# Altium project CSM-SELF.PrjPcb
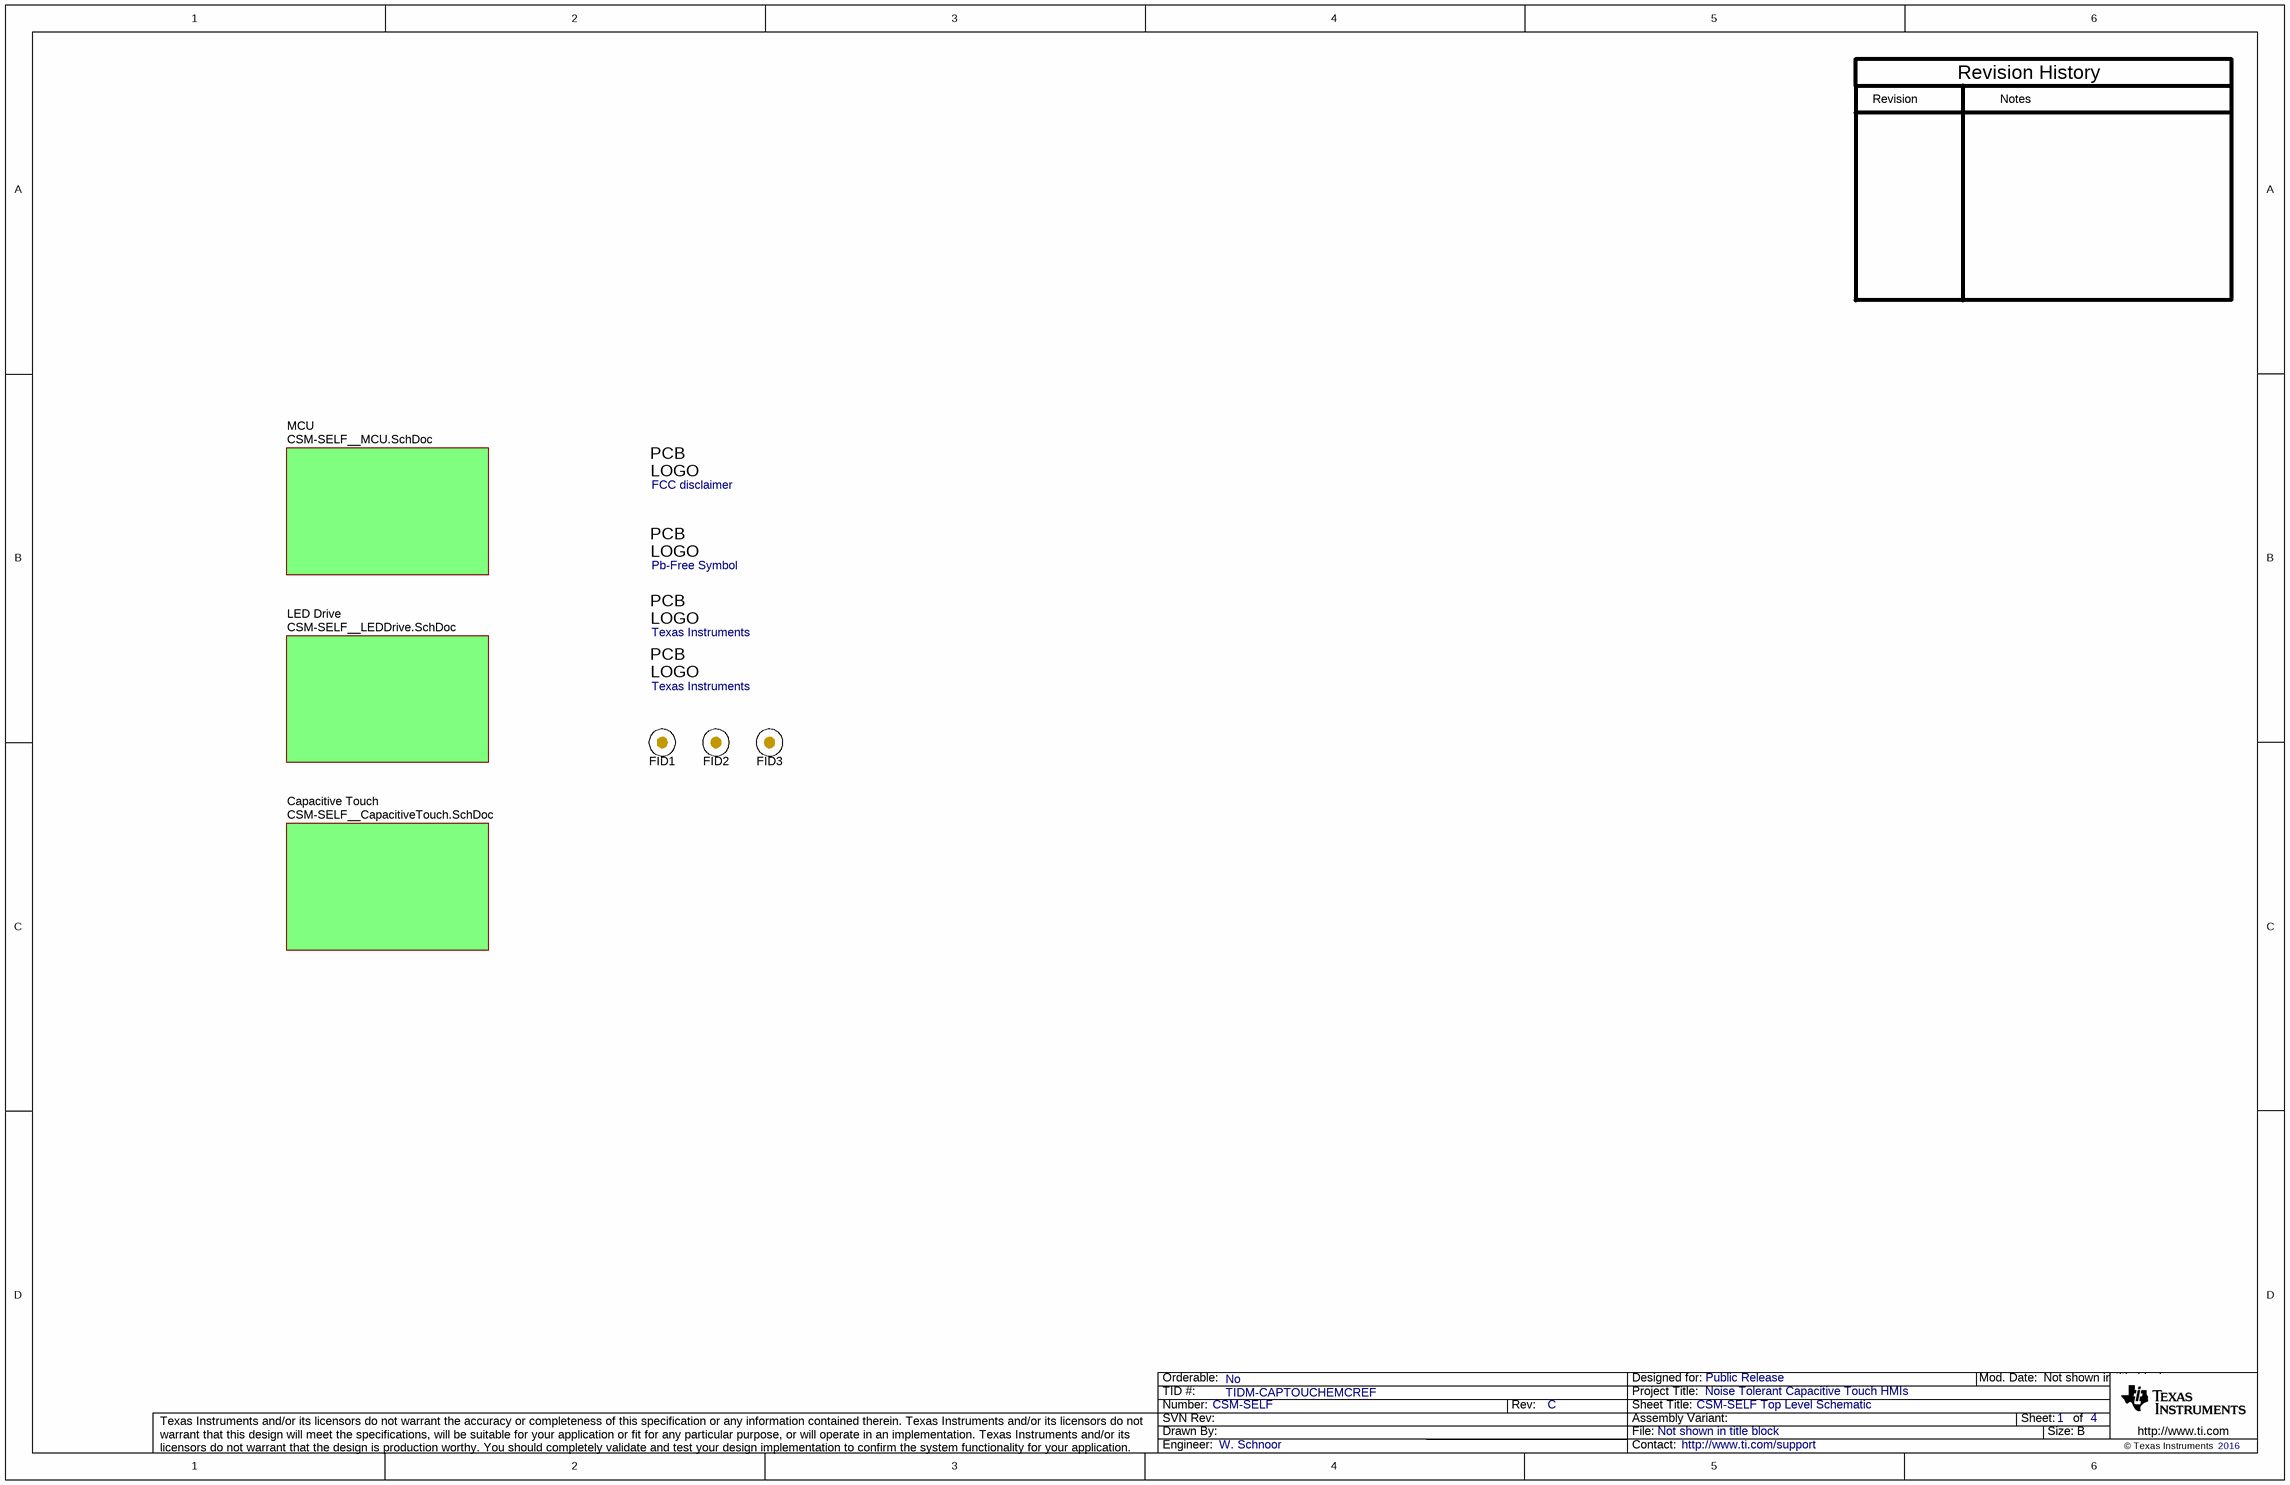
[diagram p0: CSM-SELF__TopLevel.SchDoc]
TID: TIDM-CAPTOUCHEMCREF; TechSupport: http://www.ti.com/support; SCH_Rev: C; PRJ_Title: Noise Tolerant Capacitive Touch HMIs; PRJ_Number: CSM-SELF; PRJ_Engineer: W. Schnoor; PRJ_Customer: Public Release; PCB_Rev: C; PCB_Layout: W. Schnoor; EVM_Orderable: No; CopyrightYear: 2016
4 sheets, 115 parts. Net scope: global (net labels, ports and power ports of the same name join across sheets).
Board file: CSM-SELF.PcbDoc
Sheets:
  CSM-SELF__TopLevel.SchDoc
    Capacitive Touch = CSM-SELF__CapacitiveTouch.SchDoc
    LED Drive = CSM-SELF__LEDDrive.SchDoc
    MCU = CSM-SELF__MCU.SchDoc

## Sheet CSM-SELF__TopLevel.SchDoc: CSM-SELF Top Level Schematic
size 431 x 279 mm; Date: Not shown in title block; ApprovedBy: Not shown in title block; CheckedBy: Not shown in title block; Author: Not shown in title block; CompanyName: Not shown in title block; Engineer: Not shown in title block; Organization: Not shown in title block; Address1: Not shown in title block; Address2: Not shown in title block; Address3: Not shown in title block; Address4: Not shown in title block; DocumentNumber: 1; Revision: Use project parameter SCH_Rev; SheetNumber: 1; SheetTotal: 4; PageSetup: Record=PageOptions¦CenterHorizontal=True¦CenterVertical=True¦PrintScale=1.00¦XCorrection=1.00¦YCorrection=1.00¦PrintKind=0¦BorderSize=5000000¦LeftOffset=0¦BottomOffset=0¦Orientation=2¦PaperLength=1000¦PaperWidth=1000¦Scale=100¦PaperSource=15¦PrintQuality=600¦MediaType=1¦DitherType=10¦PaperKind=Letter¦PrintScaleMode=1

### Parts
FCCLogo  FCC disclaimer  [FCC_disclaimer]  (no BOM)
FID1  Fiducial  [Fiducial10-30]  (value not drawn)
FID2  Fiducial  [Fiducial10-30]  (value not drawn)
FID3  Fiducial  [Fiducial10-30]  (value not drawn)
PbFreeLogo  Pb-Free Symbol  [Pb-Free_Overlay_Medium]  (no BOM)
TILogo  Texas Instruments  [TI_Stacked_Overlay_Medium]  (no BOM)
TILogoBack  Texas Instruments  [TI_Stacked_Overlay_Medium]  (no BOM)

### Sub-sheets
Capacitive Touch = CSM-SELF__CapacitiveTouch.SchDoc: no entries
LED Drive = CSM-SELF__LEDDrive.SchDoc: no entries
MCU = CSM-SELF__MCU.SchDoc: no entries

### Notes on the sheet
- Revision
- Notes
- Revision History

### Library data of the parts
FCCLogo = FCC_disclaimer: SymbolCreator: codlsc
FID1-FID3 = Fiducial: Fiducial mark.  There is nothing to buy or mount.; SymbolCreator: codlsc
PbFreeLogo = Pb-Free: SymbolCreator: a0412235
TILogo TILogoBack = TI_Logo: Texas Instrument Corporate Signature; SymbolCreator: a0412235

## Sheet CSM-SELF__CapacitiveTouch.SchDoc: CSM-SELF Capacitive Touch Schematic
size 431 x 279 mm; Date: Not shown in title block; ApprovedBy: Not shown in title block; CheckedBy: Not shown in title block; Author: Not shown in title block; CompanyName: Not shown in title block; DrawnBy: W. Schnoor; Engineer: Not shown in title block; Organization: Not shown in title block; Address1: Not shown in title block; Address2: Not shown in title block; Address3: Not shown in title block; Address4: Not shown in title block; DocumentNumber: 1; Revision: Use project parameter SCH_Rev; SheetNumber: 2; SheetTotal: 4; PageSetup: Record=PageOptions¦CenterHorizontal=True¦CenterVertical=True¦PrintScale=1.00¦XCorrection=1.00¦YCorrection=1.00¦PrintKind=0¦BorderSize=5000000¦LeftOffset=0¦BottomOffset=0¦Orientation=2¦PaperLength=1000¦PaperWidth=1000¦Scale=100¦PaperSource=15¦PrintQuality=600¦MediaType=1¦DitherType=10¦PaperKind=Letter¦PrintScaleMode=1
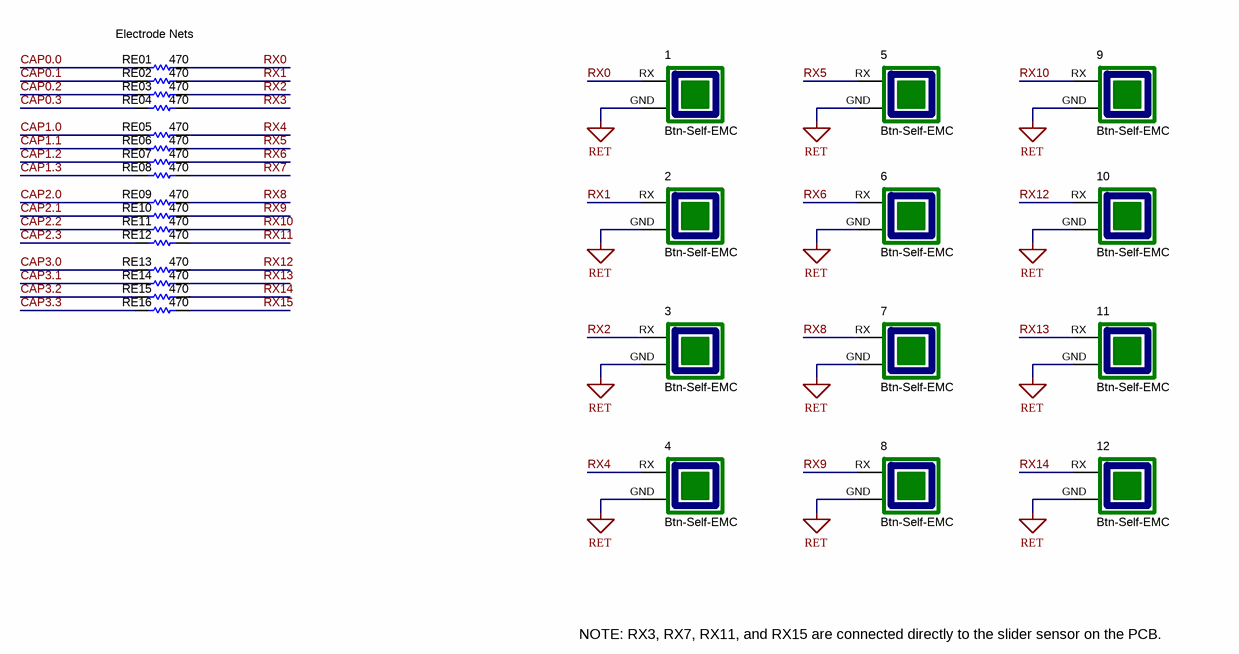
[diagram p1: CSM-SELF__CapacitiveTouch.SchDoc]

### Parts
1  Btn-Self-EMC  [btn-self-emc]
2  Btn-Self-EMC  [btn-self-emc]
3  Btn-Self-EMC  [btn-self-emc]
4  Btn-Self-EMC  [btn-self-emc]
5  Btn-Self-EMC  [btn-self-emc]
6  Btn-Self-EMC  [btn-self-emc]
7  Btn-Self-EMC  [btn-self-emc]
8  Btn-Self-EMC  [btn-self-emc]
9  Btn-Self-EMC  [btn-self-emc]
10  Btn-Self-EMC  [btn-self-emc]
11  Btn-Self-EMC  [btn-self-emc]
12  Btn-Self-EMC  [btn-self-emc]
RE01  ValueDisplayed: 470  [0402]  (hidden comment: CRCW0402470RJNED)
RE02  ValueDisplayed: 470  [0402]  (hidden comment: CRCW0402470RJNED)
RE03  ValueDisplayed: 470  [0402]  (hidden comment: CRCW0402470RJNED)
RE04  ValueDisplayed: 470  [0402]  (hidden comment: CRCW0402470RJNED)
RE05  ValueDisplayed: 470  [0402]  (hidden comment: CRCW0402470RJNED)
RE06  ValueDisplayed: 470  [0402]  (hidden comment: CRCW0402470RJNED)
RE07  ValueDisplayed: 470  [0402]  (hidden comment: CRCW0402470RJNED)
RE08  ValueDisplayed: 470  [0402]  (hidden comment: CRCW0402470RJNED)
RE09  ValueDisplayed: 470  [0402]  (hidden comment: CRCW0402470RJNED)
RE10  ValueDisplayed: 470  [0402]  (hidden comment: CRCW0402470RJNED)
RE11  ValueDisplayed: 470  [0402]  (hidden comment: CRCW0402470RJNED)
RE12  ValueDisplayed: 470  [0402]  (hidden comment: CRCW0402470RJNED)
RE13  ValueDisplayed: 470  [0402]  (hidden comment: CRCW0402470RJNED)
RE14  ValueDisplayed: 470  [0402]  (hidden comment: CRCW0402470RJNED)
RE15  ValueDisplayed: 470  [0402]  (hidden comment: CRCW0402470RJNED)
RE16  ValueDisplayed: 470  [0402]  (hidden comment: CRCW0402470RJNED)

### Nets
RET: 1.GND 2.GND 3.GND 4.GND 5.GND 6.GND 7.GND 8.GND 9.GND 10.GND 11.GND 12.GND
CAP0.0: RE01.1
CAP0.1: RE02.1
CAP0.2: RE03.1
CAP0.3: RE04.1
CAP1.0: RE05.1
CAP1.1: RE06.1
CAP1.2: RE07.1
CAP1.3: RE08.1
CAP2.0: RE09.1
CAP2.1: RE10.1
CAP2.2: RE11.1
CAP2.3: RE12.1
CAP3.0: RE13.1
CAP3.1: RE14.1
CAP3.2: RE15.1
CAP3.3: RE16.1
RX0: 1.RX RE01.2
RX1: 2.RX RE02.2
RX2: 3.RX RE03.2
RX3: RE04.2
RX4: 4.RX RE05.2
RX5: 5.RX RE06.2
RX6: 6.RX RE07.2
RX7: RE08.2
RX8: 7.RX RE09.2
RX9: 8.RX RE10.2
RX10: 9.RX RE11.2
RX11: RE12.2
RX12: 10.RX RE13.2
RX13: 11.RX RE14.2
RX14: 12.RX RE15.2
RX15: RE16.2

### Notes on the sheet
- Electrode Nets
- NOTE: RX3, RX7, RX11, and RX15 are connected directly to the slider sensor on the PCB.

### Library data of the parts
1-12 = btn-self-emc: Capacitive Button, Self Capacitance, 2-Layer, High EMC; Manufacturer: Used in BOM report; SymbolCreator: Use a-id; CompType: Used in some BOM reports.  Useful for finding later.; U/M: EA, IN, or GM
RE01 RE02 RE03 RE04 RE05 RE06 RE07 RE08 RE09-RE16 = CRCW0402470RJNED: RES, 470, 5%, 0.063 W, 0402; Manufacturer: Vishay-Dale; CompType: Resistor; Value: 470; Value_Code: 470R; Tolerance_%: 5; Power_W: 0.063; Value2: 0.063W; VDC_V: 50; TempCo: 200 ppm/C; EIA_Code: E24; U/M: EA; AEC Category: Q200

## Sheet CSM-SELF__LEDDrive.SchDoc
size 431 x 279 mm; Date: Not shown in title block; ApprovedBy: Not shown in title block; CheckedBy: Not shown in title block; Author: Not shown in title block; CompanyName: Not shown in title block; DrawnBy: W. Schnoor; Engineer: Not shown in title block; Organization: Not shown in title block; Address1: Not shown in title block; Address2: Not shown in title block; Address3: Not shown in title block; Address4: Not shown in title block; DocumentNumber: 1; Revision: Use project parameter SCH_Rev; SheetNumber: 3; SheetTotal: 4; PageSetup: Record=PageOptions¦CenterHorizontal=True¦CenterVertical=True¦PrintScale=1.00¦XCorrection=1.00¦YCorrection=1.00¦PrintKind=0¦BorderSize=5000000¦LeftOffset=0¦BottomOffset=0¦Orientation=2¦PaperLength=1000¦PaperWidth=1000¦Scale=100¦PaperSource=15¦PrintQuality=600¦MediaType=1¦DitherType=10¦PaperKind=Letter¦PrintScaleMode=1
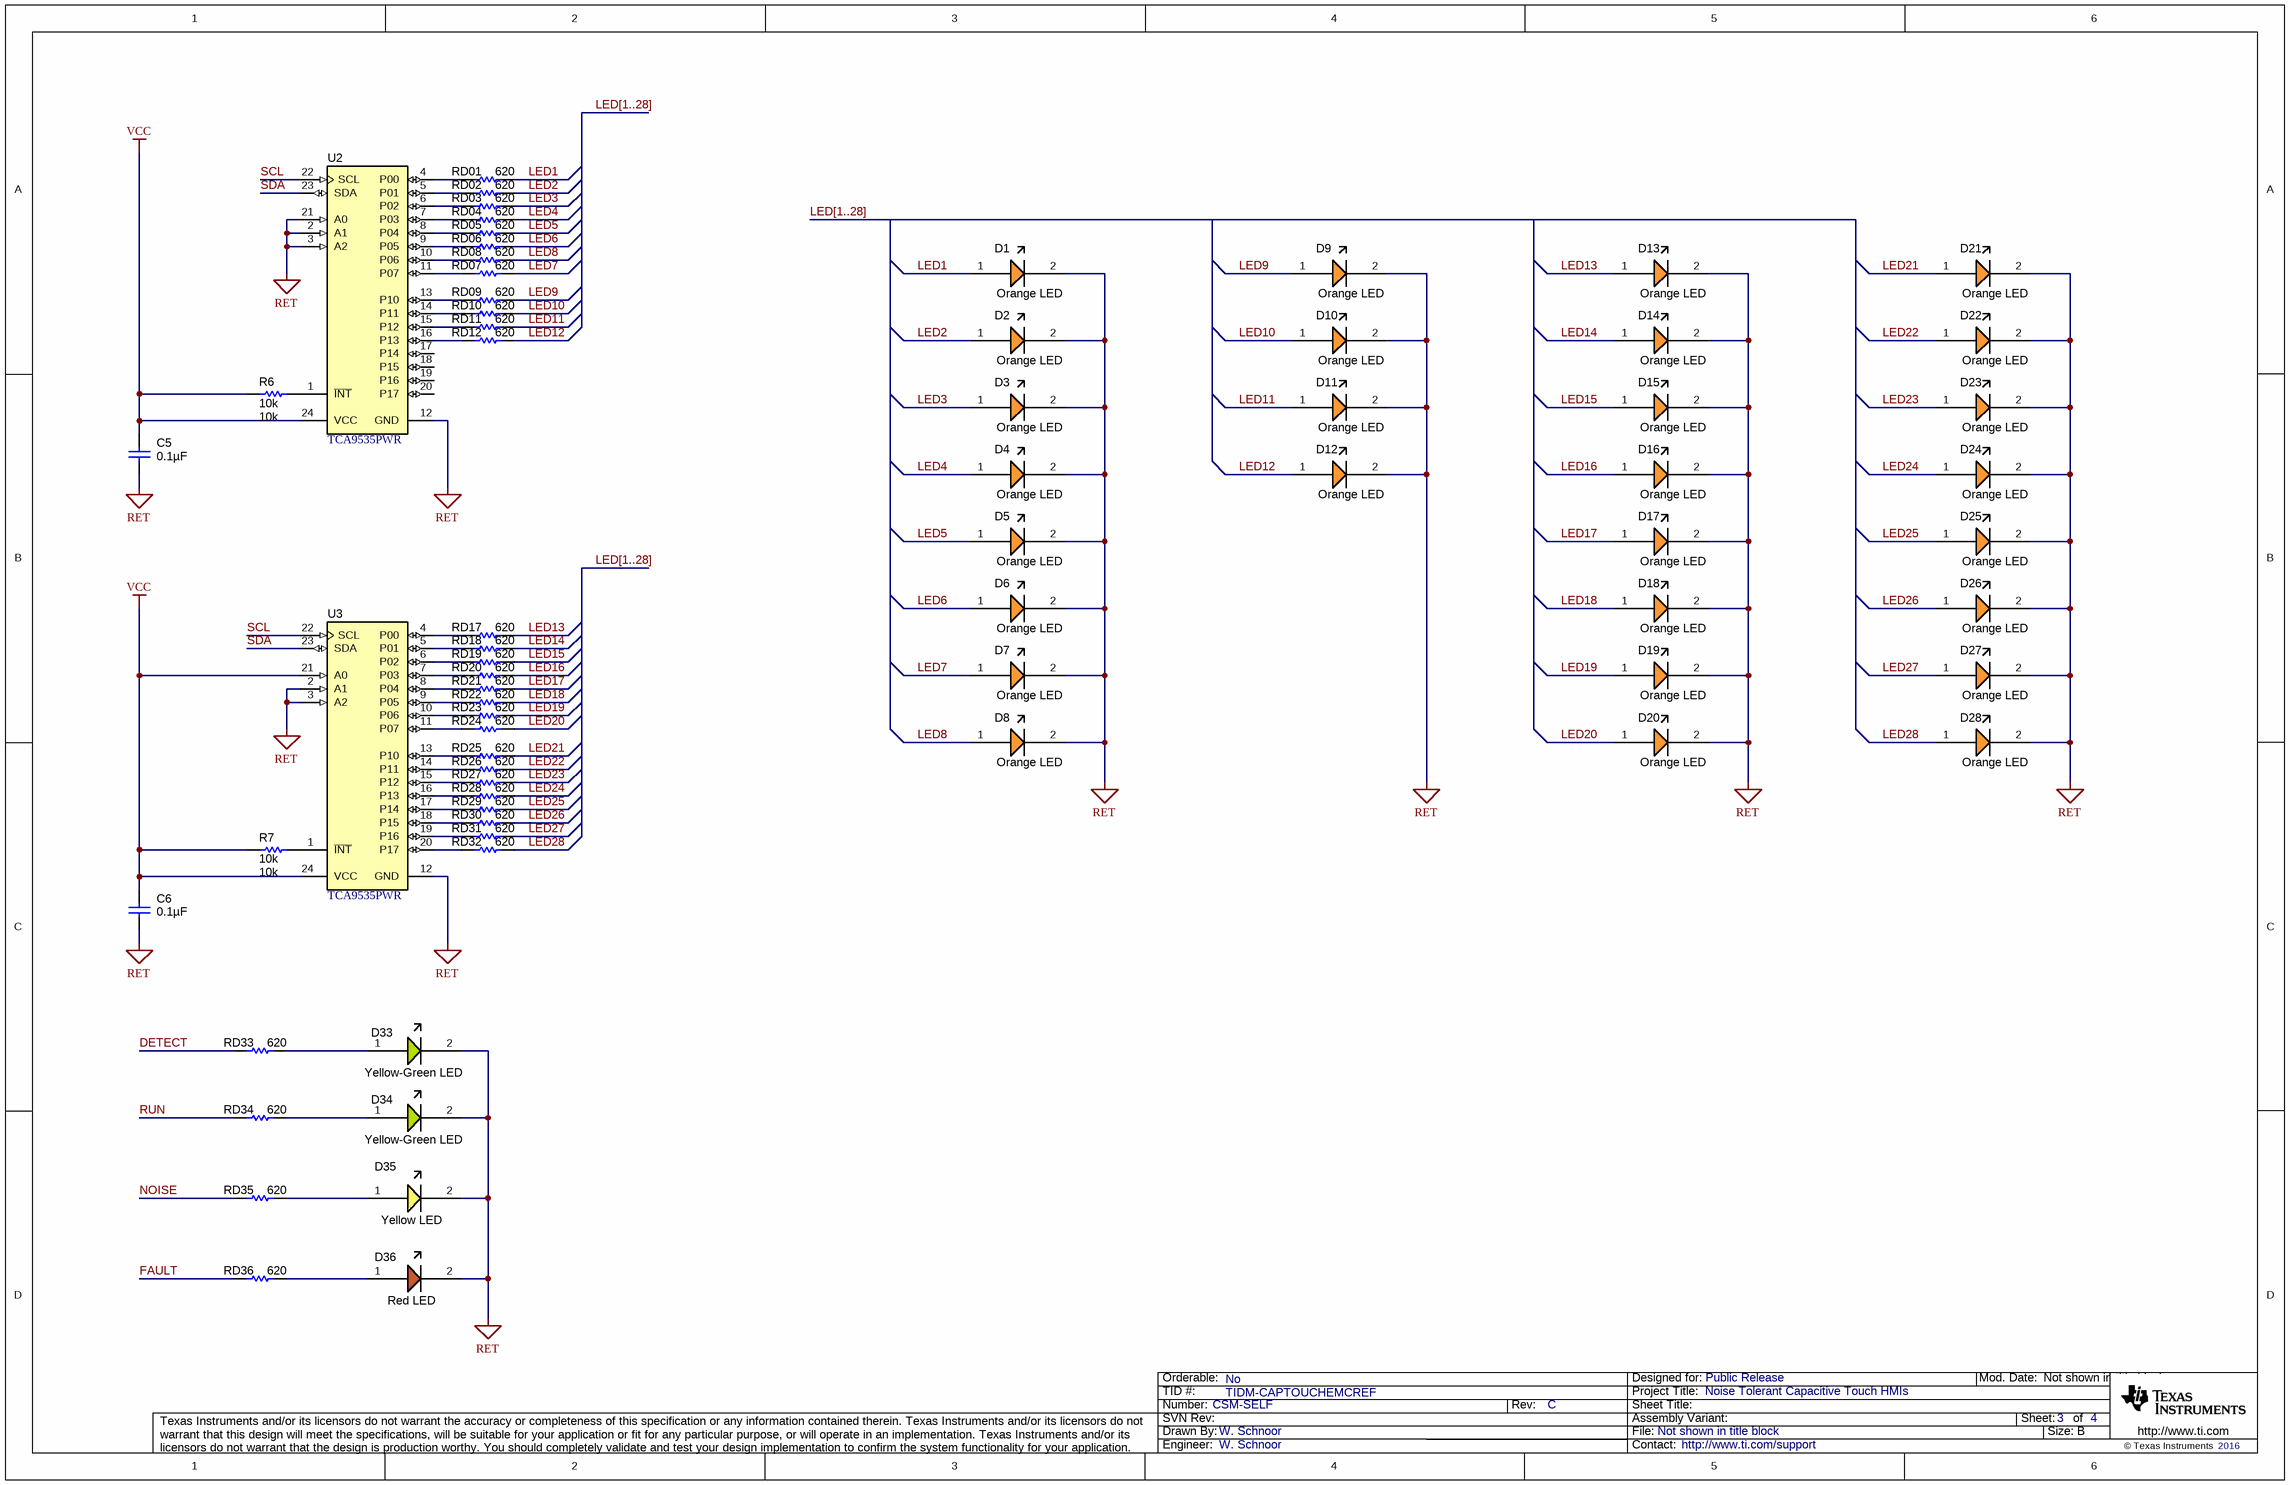
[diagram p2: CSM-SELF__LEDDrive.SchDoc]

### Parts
C5  ValueDisplayed: 0.1µF  [0603]  (hidden comment: 0603YC104JAT2A)
C6  ValueDisplayed: 0.1µF  [0603]  (hidden comment: 0603YC104JAT2A)
D1  Orange LED  [1206_ReverseMount_LED]
D2  Orange LED  [1206_ReverseMount_LED]
D3  Orange LED  [1206_ReverseMount_LED]
D4  Orange LED  [1206_ReverseMount_LED]
D5  Orange LED  [1206_ReverseMount_LED]
D6  Orange LED  [1206_ReverseMount_LED]
D7  Orange LED  [1206_ReverseMount_LED]
D8  Orange LED  [1206_ReverseMount_LED]
D9  Orange LED  [1206_ReverseMount_LED]
D10  Orange LED  [1206_ReverseMount_LED]
D11  Orange LED  [1206_ReverseMount_LED]
D12  Orange LED  [1206_ReverseMount_LED]
D13  Orange LED  [1206_ReverseMount_LED]
D14  Orange LED  [1206_ReverseMount_LED]
D15  Orange LED  [1206_ReverseMount_LED]
D16  Orange LED  [1206_ReverseMount_LED]
D17  Orange LED  [1206_ReverseMount_LED]
D18  Orange LED  [1206_ReverseMount_LED]
D19  Orange LED  [1206_ReverseMount_LED]
D20  Orange LED  [1206_ReverseMount_LED]
D21  Orange LED  [1206_ReverseMount_LED]
D22  Orange LED  [1206_ReverseMount_LED]
D23  Orange LED  [1206_ReverseMount_LED]
D24  Orange LED  [1206_ReverseMount_LED]
D25  Orange LED  [1206_ReverseMount_LED]
D26  Orange LED  [1206_ReverseMount_LED]
D27  Orange LED  [1206_ReverseMount_LED]
D28  Orange LED  [1206_ReverseMount_LED]
D33  Yellow-Green LED  [1206_ReverseMount_LED]
D34  Yellow-Green LED  [1206_ReverseMount_LED]
D35  Yellow LED  [1206_ReverseMount_LED]
D36  Red LED  [1206_ReverseMount_LED]
R6  value 10k  [0603]  (hidden comment: CRCW060310K0JNEA)
R7  value 10k  [0603]  (hidden comment: CRCW060310K0JNEA)
RD01  ValueDisplayed: 620  [0402]  (hidden comment: CRCW0402620RJNED)
RD02  ValueDisplayed: 620  [0402]  (hidden comment: CRCW0402620RJNED)
RD03  ValueDisplayed: 620  [0402]  (hidden comment: CRCW0402620RJNED)
RD04  ValueDisplayed: 620  [0402]  (hidden comment: CRCW0402620RJNED)
RD05  ValueDisplayed: 620  [0402]  (hidden comment: CRCW0402620RJNED)
RD06  ValueDisplayed: 620  [0402]  (hidden comment: CRCW0402620RJNED)
RD07  ValueDisplayed: 620  [0402]  (hidden comment: CRCW0402620RJNED)
RD08  ValueDisplayed: 620  [0402]  (hidden comment: CRCW0402620RJNED)
RD09  ValueDisplayed: 620  [0402]  (hidden comment: CRCW0402620RJNED)
RD10  ValueDisplayed: 620  [0402]  (hidden comment: CRCW0402620RJNED)
RD11  ValueDisplayed: 620  [0402]  (hidden comment: CRCW0402620RJNED)
RD12  ValueDisplayed: 620  [0402]  (hidden comment: CRCW0402620RJNED)
RD17  ValueDisplayed: 620  [0402]  (hidden comment: CRCW0402620RJNED)
RD18  ValueDisplayed: 620  [0402]  (hidden comment: CRCW0402620RJNED)
RD19  ValueDisplayed: 620  [0402]  (hidden comment: CRCW0402620RJNED)
RD20  ValueDisplayed: 620  [0402]  (hidden comment: CRCW0402620RJNED)
RD21  ValueDisplayed: 620  [0402]  (hidden comment: CRCW0402620RJNED)
RD22  ValueDisplayed: 620  [0402]  (hidden comment: CRCW0402620RJNED)
RD23  ValueDisplayed: 620  [0402]  (hidden comment: CRCW0402620RJNED)
RD24  ValueDisplayed: 620  [0402]  (hidden comment: CRCW0402620RJNED)
RD25  ValueDisplayed: 620  [0402]  (hidden comment: CRCW0402620RJNED)
RD26  ValueDisplayed: 620  [0402]  (hidden comment: CRCW0402620RJNED)
RD27  ValueDisplayed: 620  [0402]  (hidden comment: CRCW0402620RJNED)
RD28  ValueDisplayed: 620  [0402]  (hidden comment: CRCW0402620RJNED)
RD29  ValueDisplayed: 620  [0402]  (hidden comment: CRCW0402620RJNED)
RD30  ValueDisplayed: 620  [0402]  (hidden comment: CRCW0402620RJNED)
RD31  ValueDisplayed: 620  [0402]  (hidden comment: CRCW0402620RJNED)
RD32  ValueDisplayed: 620  [0402]  (hidden comment: CRCW0402620RJNED)
RD33  ValueDisplayed: 620  [0402]  (hidden comment: CRCW0402620RJNED)
RD34  ValueDisplayed: 620  [0402]  (hidden comment: CRCW0402620RJNED)
RD35  ValueDisplayed: 620  [0402]  (hidden comment: CRCW0402620RJNED)
RD36  ValueDisplayed: 620  [0402]  (hidden comment: CRCW0402620RJNED)
U2  TCA9535PWR  [PW0024A_N]
U3  TCA9535PWR  [PW0024A_N]

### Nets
RET: C5.2 C6.2 D1.2(Cathode) D2.2(Cathode) D3.2(Cathode) D4.2(Cathode) D5.2(Cathode) D6.2(Cathode) D7.2(Cathode) D8.2(Cathode) D9.2(Cathode) D10.2(Cathode) D11.2(Cathode) D12.2(Cathode) D13.2(Cathode) D14.2(Cathode) D15.2(Cathode) D16.2(Cathode) D17.2(Cathode) D18.2(Cathode) D19.2(Cathode) D20.2(Cathode) D21.2(Cathode) D22.2(Cathode) D23.2(Cathode) D24.2(Cathode) D25.2(Cathode) D26.2(Cathode) D27.2(Cathode) D28.2(Cathode) D33.2(Cathode) D34.2(Cathode) D35.2(Cathode) D36.2(Cathode) U2.2(A1) U2.3(A2) U2.12(GND) U2.21(A0) U3.2(A1) U3.3(A2) U3.12(GND)
VCC: C5.1 C6.1 R6.1 R7.1 U2.24(VCC) U3.21(A0) U3.24(VCC)
DETECT: RD33.1
FAULT: RD36.1
LED1: D1.1(Anode) RD01.2
LED2: D2.1(Anode) RD02.2
LED3: D3.1(Anode) RD03.2
LED4: D4.1(Anode) RD04.2
LED5: D5.1(Anode) RD05.2
LED6: D6.1(Anode) RD06.2
LED7: D7.1(Anode) RD07.2
LED8: D8.1(Anode) RD08.2
LED9: D9.1(Anode) RD09.2
LED10: D10.1(Anode) RD10.2
LED11: D11.1(Anode) RD11.2
LED12: D12.1(Anode) RD12.2
LED13: D13.1(Anode) RD17.2
LED14: D14.1(Anode) RD18.2
LED15: D15.1(Anode) RD19.2
LED16: D16.1(Anode) RD20.2
LED17: D17.1(Anode) RD21.2
LED18: D18.1(Anode) RD22.2
LED19: D19.1(Anode) RD23.2
LED20: D20.1(Anode) RD24.2
LED21: D21.1(Anode) RD25.2
LED22: D22.1(Anode) RD26.2
LED23: D23.1(Anode) RD27.2
LED24: D24.1(Anode) RD28.2
LED25: D25.1(Anode) RD29.2
LED26: D26.1(Anode) RD30.2
LED27: D27.1(Anode) RD31.2
LED28: D28.1(Anode) RD32.2
NOISE: RD35.1
RUN: RD34.1
SCL: U2.22(SCL) U3.22(SCL)
SDA: U2.23(SDA) U3.23(SDA)
NetD33_1: D33.1(Anode) RD33.2
NetD34_1: D34.1(Anode) RD34.2
NetD35_1: D35.1(Anode) RD35.2
NetD36_1: D36.1(Anode) RD36.2
NetR6_2: R6.2 U2.1(~{INT})
NetR7_2: R7.2 U3.1(~{INT})
NetRD01_1: RD01.1 U2.4(P00)
NetRD02_1: RD02.1 U2.5(P01)
NetRD03_1: RD03.1 U2.6(P02)
NetRD04_1: RD04.1 U2.7(P03)
NetRD05_1: RD05.1 U2.8(P04)
NetRD06_1: RD06.1 U2.9(P05)
NetRD07_1: RD07.1 U2.11(P07)
NetRD08_1: RD08.1 U2.10(P06)
NetRD09_1: RD09.1 U2.13(P10)
NetRD10_1: RD10.1 U2.14(P11)
NetRD11_1: RD11.1 U2.15(P12)
NetRD12_1: RD12.1 U2.16(P13)
NetRD17_1: RD17.1 U3.4(P00)
NetRD18_1: RD18.1 U3.5(P01)
NetRD19_1: RD19.1 U3.6(P02)
NetRD20_1: RD20.1 U3.7(P03)
NetRD21_1: RD21.1 U3.8(P04)
NetRD22_1: RD22.1 U3.9(P05)
NetRD23_1: RD23.1 U3.10(P06)
NetRD24_1: RD24.1 U3.11(P07)
NetRD25_1: RD25.1 U3.13(P10)
NetRD26_1: RD26.1 U3.14(P11)
NetRD27_1: RD27.1 U3.15(P12)
NetRD28_1: RD28.1 U3.16(P13)
NetRD29_1: RD29.1 U3.17(P14)
NetRD30_1: RD30.1 U3.18(P15)
NetRD31_1: RD31.1 U3.19(P16)
NetRD32_1: RD32.1 U3.20(P17)

Not connected (* = marked no-connect by the designer): U2 17(P14) 18(P15) 19(P16) 20(P17)

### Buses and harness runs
bus LED[1..28]

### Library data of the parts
C5 C6 = 0603YC104JAT2A: CAP, CERM, 0.1 µF, 16 V, +/- 5%, X7R, 0603; Manufacturer: AVX; Polarized: N; CompType: Capacitor; Value: 0.1uF; U/M: EA; Cap_F: 0.0000001; Tolerance_%: 5; ESR_ohm: 0.039; Value1: 0.039 ohm; VDC_V: 16; Value2: 16V; TaMin_C: -55; TaMax_C: 125; AEC Category: Q200
D1-D28 = 597-6201-607F: LED, Orange, SMD, Reverse Mount, 1206; Manufacturer: Dialight; SymbolCreator: a0273983; U/M: EA, IN, or GM; Vf: 2.0-2.4V
D33 D34 = 597-6501-607F: LED, Yellow-Green, SMD, Reverse Mount, 1206; Manufacturer: Dialight; SymbolVersion: use current date i.e. 2008-05-20; SymbolCreator: a0273983; U/M: EA, IN, or GM; Vf: 1.8V-2.4V
D35 = 597-6401-607F: LED, Yellow, SMD, Reverse Mount, 1206; Manufacturer: Dialight; SymbolVersion: use current date i.e. 2008-05-20; SymbolCreator: a0273983; U/M: EA, IN, or GM; Vf: 2.0-3.4V
D36 = 597-6001-607F: LED, Red, SMD, Reverse Mount, 1206; Manufacturer: Dialight; SymbolCreator: a0273983; U/M: EA, IN, or GM; Vf: 2.0V-2.4V
R6 R7 = CRCW060310K0JNEA: RES, 10 k, 5%, 0.1 W, 0603; Manufacturer: Vishay-Dale; CompType: Resistor; Res_ohm: 10000; Value_Code: 10k0; Tolerance_%: 5; Power_W: 0.1; Value2: 0.1W; VDC_V: 75; TempCo: 200 ppm/C; EIA_Code: E24; U/M: EA; AEC Category: Q200
RD01 RD02 RD03 RD04 RD05 RD06 RD07 RD08 RD09-RD12 RD17-RD36 = CRCW0402620RJNED: RES, 620, 5%, 0.063 W, 0402; Manufacturer: Vishay-Dale; CompType: Resistor; Value: 620; Value_Code: 620R; Tolerance_%: 5; Power_W: 0.063; Value2: 0.063W; VDC_V: 50; TempCo: 200 ppm/C; EIA_Code: E24; U/M: EA; AEC Category: Q200
U2 U3 = TCA9535PWR: Remote 16-Bit I2C and SMBus, Low-Power I/O Expander with Interrupt Output and Config Register, 1.65 to 5.5 V, -40 to 85 degC, 24-pin TSSOP (PW), Green (RoHS & no Sb/Br); Manufacturer: Texas Instruments; Alternate PartNumber: Equivalent; SubFamily: I2C IO Expander; Interrupt Output: Yes; Max Frequency(kHz): 400; I2C Address: 0100 xxx; # of I/Os: 16

## Sheet CSM-SELF__MCU.SchDoc: CSM-SELF MCU Schematic
size 431 x 279 mm; Date: Not shown in title block; ApprovedBy: Not shown in title block; CheckedBy: Not shown in title block; Author: Not shown in title block; CompanyName: Not shown in title block; DrawnBy: W. Schnoor; Engineer: Not shown in title block; Organization: Not shown in title block; Address1: Not shown in title block; Address2: Not shown in title block; Address3: Not shown in title block; Address4: Not shown in title block; DocumentNumber: 1; Revision: Use project parameter SCH_Rev; SheetNumber: 4; SheetTotal: 4; PageSetup: Record=PageOptions¦CenterHorizontal=True¦CenterVertical=True¦PrintScale=1.00¦XCorrection=1.00¦YCorrection=1.00¦PrintKind=0¦BorderSize=5000000¦LeftOffset=0¦BottomOffset=0¦Orientation=2¦PaperLength=1000¦PaperWidth=1000¦Scale=100¦PaperSource=15¦PrintQuality=600¦MediaType=1¦DitherType=10¦PaperKind=Letter¦PrintScaleMode=1
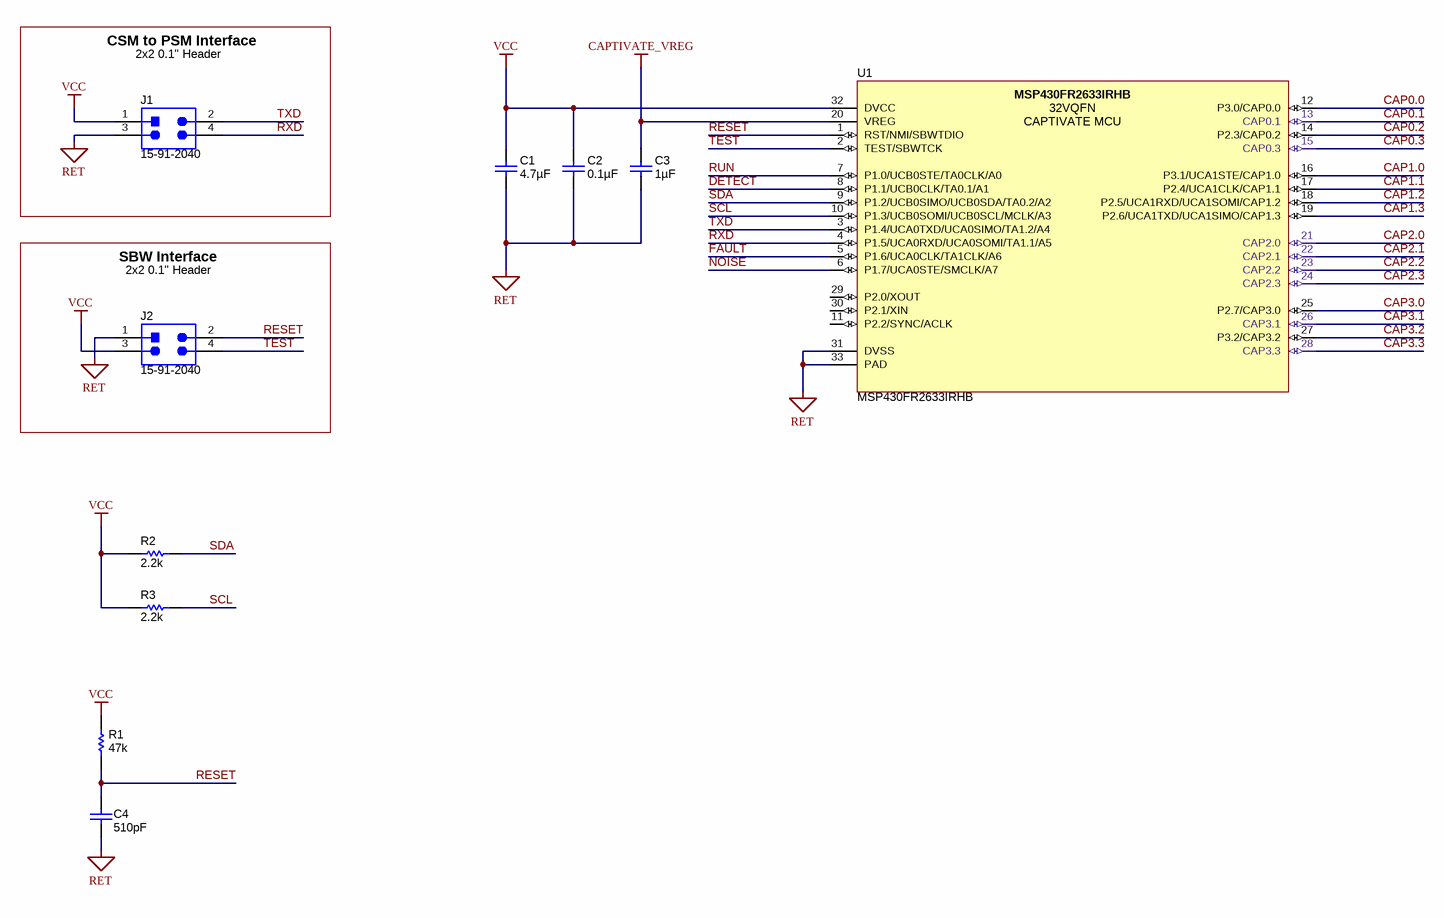
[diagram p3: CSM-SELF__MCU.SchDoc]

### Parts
C1  ValueDisplayed: 4.7µF  [0402]  (hidden comment: C1005X5R0J475M050BC)
C2  ValueDisplayed: 0.1µF  [0402]  (hidden comment: C1005X5R0J104K)
C3  ValueDisplayed: 1µF  [0402]  (hidden comment: C1005X5R0J105M)
C4  ValueDisplayed: 510pF  [0402]  (hidden comment: GRM1555C1E511JA01D)
J1  15-91-2040  [Molex_15-91-2040]
J2  15-91-2040  [Molex_15-91-2040]
R1  ValueDisplayed: 47k  [0402]  (hidden comment: CRCW040247K0JNED)
R2  ValueDisplayed: 2.2k  [0402]  (hidden comment: CRCW04022K20JNED)
R3  ValueDisplayed: 2.2k  [0402]  (hidden comment: CRCW04022K20JNED)
U1  MSP430FR2633IRHB  [RHB0032E_NV]

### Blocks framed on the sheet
CSM to PSM Interface: J1
SBW Interface: J2

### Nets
CAPTIVATE_VREG: C3.1 U1.20(VREG)
RET: C1.2 C2.2 C3.2 C4.2 J1.3 J2.1 U1.31(DVSS) U1.33(PAD)
VCC: C1.1 C2.1 J1.1 J2.3 R1.2 R2.1 R3.1 U1.32(DVCC)
CAP0.0: U1.12(P3.0/CAP0.0)
CAP0.1: U1.13(CAP0.1)
CAP0.2: U1.14(P2.3/CAP0.2)
CAP0.3: U1.15(CAP0.3)
CAP1.0: U1.16(P3.1/UCA1STE/CAP1.0)
CAP1.1: U1.17(P2.4/UCA1CLK/CAP1.1)
CAP1.2: U1.18(P2.5/UCA1RXD/UCA1SOMI/CAP1.2)
CAP1.3: U1.19(P2.6/UCA1TXD/UCA1SIMO/CAP1.3)
CAP2.0: U1.21(CAP2.0)
CAP2.1: U1.22(CAP2.1)
CAP2.2: U1.23(CAP2.2)
CAP2.3: U1.24(CAP2.3)
CAP3.0: U1.25(P2.7/CAP3.0)
CAP3.1: U1.26(CAP3.1)
CAP3.2: U1.27(P3.2/CAP3.2)
CAP3.3: U1.28(CAP3.3)
DETECT: U1.8(P1.1/UCB0CLK/TA0.1/A1)
FAULT: U1.5(P1.6/UCA0CLK/TA1CLK/A6)
NOISE: U1.6(P1.7/UCA0STE/SMCLK/A7)
RESET: C4.1 J2.2 R1.1 U1.1(RST/NMI/SBWTDIO)
RUN: U1.7(P1.0/UCB0STE/TA0CLK/A0)
RXD: J1.4 U1.4(P1.5/UCA0RXD/UCA0SOMI/TA1.1/A5)
SCL: R3.2 U1.10(P1.3/UCB0SOMI/UCB0SCL/MCLK/A3)
SDA: R2.2 U1.9(P1.2/UCB0SIMO/UCB0SDA/TA0.2/A2)
TEST: J2.4 U1.2(TEST/SBWTCK)
TXD: J1.2 U1.3(P1.4/UCA0TXD/UCA0SIMO/TA1.2/A4)

Not connected (* = marked no-connect by the designer): U1 11(P2.2/SYNC/ACLK) 29(P2.0/XOUT) 30(P2.1/XIN)

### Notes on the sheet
- 2x2 0.1" Header

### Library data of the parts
C1 = C1005X5R0J475M050BC: CAP, CERM, 4.7 µF, 6.3 V, +/- 20%, X5R, 0402; Manufacturer: TDK; Polarized: N; CompType: Capacitor; Value: 4.7uF; U/M: EA; Cap_F: 0.0000047; Tolerance_%: 20; Value1: Unknown; VDC_V: 6.3; Value2: 6.3V; TaMin_C: -55; TaMax_C: 85; AEC Category: Q200
C2 = C1005X5R0J104K: CAP, CERM, 0.1 µF, 6.3 V, +/- 10%, X5R, 0402; Manufacturer: TDK; Polarized: N; CompType: Capacitor; Value: 0.1uF; U/M: EA; Cap_F: 0.0000001; Tolerance_%: 10; ESR_ohm: 0.0186; Value1: 0.0186 ohm; VDC_V: 6.3; Value2: 6.3V; TaMin_C: -55; TaMax_C: 85; AEC Category: Q200
C3 = C1005X5R0J105M: CAP, CERM, 1 µF, 6.3 V, +/- 20%, X5R, 0402; Manufacturer: TDK; Polarized: N; CompType: Capacitor; Value: 1uF; U/M: EA; Cap_F: 0.000001; Tolerance_%: 20; ESR_ohm: 0.0079; Value1: 0.0079 ohm; VDC_V: 6.3; Value2: 6.3V; TaMin_C: -55; TaMax_C: 85; AEC Category: Q200
C4 = GRM1555C1E511JA01D: CAP, CERM, 510 pF, 25 V, +/- 5%, C0G/NP0, 0402; Manufacturer: MuRata; Polarized: N; CompType: Capacitor; Value: 510pF; U/M: EA; Cap_F: 0.00000000051; Tolerance_%: 5; Value1: Unknown; VDC_V: 25; Value2: 25V; TaMin_C: -55; TaMax_C: 125; AEC Category: Q200
J1 J2 = 15-91-2040: Header, 100mil, 2x2, Tin, SMT; Manufacturer: Molex; SymbolCreator: a0412235
R1 = CRCW040247K0JNED: RES, 47 k, 5%, 0.063 W, 0402; Manufacturer: Vishay-Dale; CompType: Resistor; Value: 47k; Res_ohm: 47000; Value_Code: 47k0; Tolerance_%: 5; Power_W: 0.063; Value2: 0.063W; VDC_V: 50; TempCo: 200 ppm/C; EIA_Code: E24; U/M: EA; AEC Category: Q200
R2 R3 = CRCW04022K20JNED: RES, 2.2 k, 5%, 0.063 W, 0402; Manufacturer: Vishay-Dale; CompType: Resistor; Value: 2.2k; Res_ohm: 2200; Value_Code: 2k20; Tolerance_%: 5; Power_W: 0.063; Value2: 0.063W; VDC_V: 50; TempCo: 200 ppm/C; EIA_Code: E24; U/M: EA; AEC Category: Q200
U1 = MSP430FR2633IRHB: MSP430 Captivate Microcontroller; Manufacturer: Texas Instruments; SymbolCreator: W. Schnoor; CompType: IC; U/M: EA, IN, or GM

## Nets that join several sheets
RET: CSM-SELF__CapacitiveTouch (12 pins), CSM-SELF__LEDDrive (41 pins), CSM-SELF__MCU (8 pins)
VCC: CSM-SELF__LEDDrive (7 pins), CSM-SELF__MCU (8 pins)
CAP0.0: CSM-SELF__CapacitiveTouch (RE01.1), CSM-SELF__MCU (U1.12)
CAP0.1: CSM-SELF__CapacitiveTouch (RE02.1), CSM-SELF__MCU (U1.13)
CAP0.2: CSM-SELF__CapacitiveTouch (RE03.1), CSM-SELF__MCU (U1.14)
CAP0.3: CSM-SELF__CapacitiveTouch (RE04.1), CSM-SELF__MCU (U1.15)
CAP1.0: CSM-SELF__CapacitiveTouch (RE05.1), CSM-SELF__MCU (U1.16)
CAP1.1: CSM-SELF__CapacitiveTouch (RE06.1), CSM-SELF__MCU (U1.17)
CAP1.2: CSM-SELF__CapacitiveTouch (RE07.1), CSM-SELF__MCU (U1.18)
CAP1.3: CSM-SELF__CapacitiveTouch (RE08.1), CSM-SELF__MCU (U1.19)
CAP2.0: CSM-SELF__CapacitiveTouch (RE09.1), CSM-SELF__MCU (U1.21)
CAP2.1: CSM-SELF__CapacitiveTouch (RE10.1), CSM-SELF__MCU (U1.22)
CAP2.2: CSM-SELF__CapacitiveTouch (RE11.1), CSM-SELF__MCU (U1.23)
CAP2.3: CSM-SELF__CapacitiveTouch (RE12.1), CSM-SELF__MCU (U1.24)
CAP3.0: CSM-SELF__CapacitiveTouch (RE13.1), CSM-SELF__MCU (U1.25)
CAP3.1: CSM-SELF__CapacitiveTouch (RE14.1), CSM-SELF__MCU (U1.26)
CAP3.2: CSM-SELF__CapacitiveTouch (RE15.1), CSM-SELF__MCU (U1.27)
CAP3.3: CSM-SELF__CapacitiveTouch (RE16.1), CSM-SELF__MCU (U1.28)
DETECT: CSM-SELF__LEDDrive (RD33.1), CSM-SELF__MCU (U1.8)
FAULT: CSM-SELF__LEDDrive (RD36.1), CSM-SELF__MCU (U1.5)
NOISE: CSM-SELF__LEDDrive (RD35.1), CSM-SELF__MCU (U1.6)
RUN: CSM-SELF__LEDDrive (RD34.1), CSM-SELF__MCU (U1.7)
SCL: CSM-SELF__LEDDrive (U2.22 U3.22), CSM-SELF__MCU (R3.2 U1.10)
SDA: CSM-SELF__LEDDrive (U2.23 U3.23), CSM-SELF__MCU (R2.2 U1.9)

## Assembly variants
001: not fitted FID1 FID2 FID3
